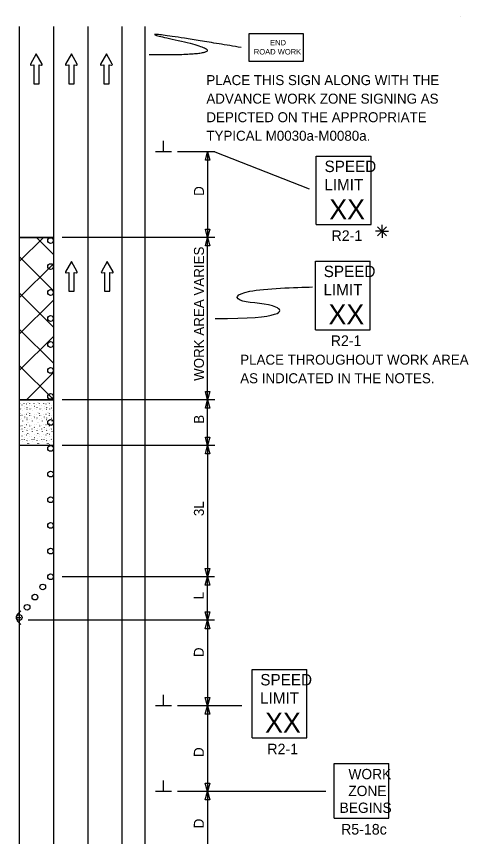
# Model space of a CAD drawing. Extents: x 16744 to 19504, y 5731 to 6974.
# Drawn here: x 17112 to 17429, y 6356 to 6931 of the extents above; entities that cross this region are included whole.
import ezdxf

# ---------------------------------------------------------------- set-up
doc = ezdxf.new("R2010")
doc.units = 0
for name, color, linetype in [('ALI_LEGAL_EX', 7, 'Continuous'), ('BORDER', 7, 'Continuous'), ('MT_SCRATCH_LEVEL_E', 7, 'Continuous'), ('PAVT_EDGE_EX', 7, 'Continuous'), ('TRAFFIC_SIGNS_PR', 7, 'Continuous'), ('TYPICAL_TEXT_DIMEN_PR', 7, 'Continuous')]:
    doc.layers.add(name, color=color, linetype=linetype)

msp = doc.modelspace()

# ---------------------------------------------------------------- linework, layer by layer
at = {"layer": 'ALI_LEGAL_EX'}
for p, q in [((17138.25, 6923.7), (17138.25, 6094.51)), ((17162.25, 6923.7), (17162.25, 6094.51))]:
    msp.add_line(p, q, dxfattribs=at)
for points in [[(17138.25, 6923.7), (17138.25, 6898.7)], [(17162.25, 6923.7), (17162.25, 6898.7)], [(17138.25, 6823.7), (17138.25, 6798.7)], [(17162.25, 6823.7), (17162.25, 6798.7)], [(17138.25, 6723.7), (17138.25, 6698.7)], [(17162.25, 6723.7), (17162.25, 6698.7)], [(17138.25, 6623.7), (17138.25, 6598.7)], [(17162.25, 6623.7), (17162.25, 6598.7)], [(17162.25, 6523.7), (17162.25, 6498.7)], [(17138.25, 6423.7), (17138.25, 6398.7)], [(17162.25, 6423.7), (17162.25, 6398.7)]]:
    msp.add_lwpolyline(points, dxfattribs=at)
at = {"layer": 'BORDER'}
msp.add_line((17423.55, 6930.8), (17423.55, 6930.8), dxfattribs=at)
at = {"layer": 'MT_SCRATCH_LEVEL_E'}
for p, q in [((17126.22, 6904.51), (17122.11, 6897.27)), ((17126.22, 6904.51), (17122.11, 6897.27)), ((17130.37, 6897.27), (17126.22, 6904.51)), ((17130.37, 6897.27), (17126.22, 6904.51)), ((17150.78, 6904.51), (17146.67, 6897.27)), ((17150.78, 6904.51), (17146.67, 6897.27)), ((17154.92, 6897.27), (17150.78, 6904.51)), ((17154.92, 6897.27), (17150.78, 6904.51)), ((17175.34, 6904.51), (17171.22, 6897.27)), ((17175.34, 6904.51), (17171.22, 6897.27)), ((17179.48, 6897.27), (17175.34, 6904.51)), ((17179.48, 6897.27), (17175.34, 6904.51)), ((17122.59, 6896.59), (17124.37, 6896.9)), ((17122.59, 6896.59), (17124.37, 6896.9)), ((17124.37, 6896.9), (17124.37, 6883.64)), ((17124.37, 6896.9), (17124.37, 6883.64)), ((17128.11, 6883.64), (17128.11, 6896.9)), ((17128.11, 6896.9), (17129.89, 6896.59)), ((17128.11, 6883.64), (17128.11, 6896.9)), ((17128.11, 6896.9), (17129.89, 6896.59)), ((17147.15, 6896.59), (17148.92, 6896.9)), ((17147.15, 6896.59), (17148.92, 6896.9)), ((17148.92, 6896.9), (17148.92, 6883.64)), ((17148.92, 6896.9), (17148.92, 6883.64)), ((17152.67, 6883.64), (17152.67, 6896.9)), ((17152.67, 6896.9), (17154.44, 6896.59)), ((17152.67, 6883.64), (17152.67, 6896.9)), ((17152.67, 6896.9), (17154.44, 6896.59)), ((17171.71, 6896.59), (17173.48, 6896.9)), ((17171.71, 6896.59), (17173.48, 6896.9)), ((17173.48, 6896.9), (17173.48, 6883.64)), ((17173.48, 6896.9), (17173.48, 6883.64)), ((17177.23, 6883.64), (17177.23, 6896.9)), ((17177.23, 6896.9), (17179, 6896.59)), ((17177.23, 6883.64), (17177.23, 6896.9)), ((17177.23, 6896.9), (17179, 6896.59)), ((17124.37, 6883.64), (17128.11, 6883.64)), ((17124.37, 6883.64), (17128.11, 6883.64)), ((17148.92, 6883.64), (17152.67, 6883.64)), ((17148.92, 6883.64), (17152.67, 6883.64)), ((17173.48, 6883.64), (17177.23, 6883.64)), ((17173.48, 6883.64), (17177.23, 6883.64)), ((17150.78, 6758.93), (17146.67, 6751.69)), ((17150.78, 6758.93), (17146.67, 6751.69)), ((17154.92, 6751.69), (17150.78, 6758.93)), ((17154.92, 6751.69), (17150.78, 6758.93)), ((17175.94, 6758.93), (17171.83, 6751.69)), ((17175.94, 6758.93), (17171.83, 6751.69)), ((17180.09, 6751.69), (17175.94, 6758.93)), ((17180.09, 6751.69), (17175.94, 6758.93)), ((17147.15, 6751.01), (17148.92, 6751.32)), ((17147.15, 6751.01), (17148.92, 6751.32)), ((17148.92, 6751.32), (17148.92, 6738.07)), ((17148.92, 6751.32), (17148.92, 6738.07)), ((17152.67, 6738.07), (17152.67, 6751.32)), ((17152.67, 6751.32), (17154.44, 6751.01)), ((17152.67, 6738.07), (17152.67, 6751.32)), ((17152.67, 6751.32), (17154.44, 6751.01)), ((17172.31, 6751.01), (17174.09, 6751.32)), ((17172.31, 6751.01), (17174.09, 6751.32)), ((17174.09, 6751.32), (17174.09, 6738.07)), ((17174.09, 6751.32), (17174.09, 6738.07)), ((17177.83, 6738.07), (17177.83, 6751.32)), ((17177.83, 6751.32), (17179.61, 6751.01)), ((17177.83, 6738.07), (17177.83, 6751.32)), ((17177.83, 6751.32), (17179.61, 6751.01)), ((17148.92, 6738.07), (17152.67, 6738.07)), ((17148.92, 6738.07), (17152.67, 6738.07)), ((17174.09, 6738.07), (17177.83, 6738.07)), ((17174.09, 6738.07), (17177.83, 6738.07))]:
    msp.add_line(p, q, dxfattribs=at)
for centre, start, end in [((17122.51, 6897.05), 150.42484, 279.96381), ((17122.51, 6897.05), 150.42484, 279.96381), ((17129.96, 6897.05), 260.03619, 29.77312), ((17129.96, 6897.05), 260.03619, 29.77312), ((17147.07, 6897.05), 150.42484, 279.96381), ((17147.07, 6897.05), 150.42484, 279.96381), ((17154.51, 6897.05), 260.03619, 29.77312), ((17154.51, 6897.05), 260.03619, 29.77312), ((17171.63, 6897.05), 150.42484, 279.96381), ((17171.63, 6897.05), 150.42484, 279.96381), ((17179.07, 6897.05), 260.03619, 29.77312), ((17179.07, 6897.05), 260.03619, 29.77312), ((17147.07, 6751.47), 150.42484, 279.96381), ((17147.07, 6751.47), 150.42484, 279.96381), ((17154.51, 6751.47), 260.03619, 29.77312), ((17154.51, 6751.47), 260.03619, 29.77312), ((17172.24, 6751.47), 150.42484, 279.96381), ((17172.24, 6751.47), 150.42484, 279.96381), ((17179.68, 6751.47), 260.03619, 29.77312), ((17179.68, 6751.47), 260.03619, 29.77312)]:
    msp.add_arc(centre, 0.463, start, end, dxfattribs=at)
at = {"layer": 'PAVT_EDGE_EX'}
for p, q in [((17114.25, 6923.7), (17114.25, 6094.51)), ((17186.25, 6923.7), (17186.25, 6094.51)), ((17202.25, 6923.7), (17202.25, 6094.51)), ((17114.25, 6775.79), (17138.25, 6775.79)), ((17114.25, 6758.89), (17131.15, 6775.79)), ((17138.34, 6775.79), (17114.34, 6775.79)), ((17138.25, 6763.97), (17126.44, 6775.79)), ((17138.25, 6738.52), (17114.25, 6762.52)), ((17114.25, 6733.43), (17138.25, 6757.43)), ((17138.25, 6713.06), (17114.25, 6737.06)), ((17114.25, 6707.98), (17138.25, 6731.98)), ((17138.25, 6687.61), (17114.25, 6711.61)), ((17114.25, 6682.52), (17138.25, 6706.52)), ((17138.25, 6662.15), (17114.25, 6686.15)), ((17119.25, 6662.06), (17138.34, 6681.15)), ((17138.25, 6662.06), (17114.25, 6662.06)), ((17138.34, 6662.06), (17114.34, 6662.06)), ((17114.34, 6662.06), (17138.34, 6662.06)), ((17114.65, 6658.24), (17114.6, 6658.16)), ((17114.73, 6659.51), (17114.68, 6659.62)), ((17116.18, 6658.38), (17116.13, 6658.3)), ((17116.75, 6661.7), (17116.7, 6661.82)), ((17117.8, 6659.21), (17117.74, 6659.33)), ((17119.25, 6659.06), (17119.19, 6658.98)), ((17120.12, 6660.44), (17120.06, 6660.36)), ((17120.85, 6660.47), (17120.8, 6660.39)), ((17121.54, 6658.24), (17121.48, 6658.16)), ((17121.62, 6659.51), (17121.56, 6659.62)), ((17123.07, 6658.38), (17123.01, 6658.3)), ((17123.64, 6661.7), (17123.58, 6661.82)), ((17124.68, 6659.21), (17124.63, 6659.33)), ((17126.13, 6659.06), (17126.08, 6658.98)), ((17127, 6660.44), (17126.95, 6660.36)), ((17127.74, 6660.47), (17127.69, 6660.39)), ((17128.42, 6658.24), (17128.37, 6658.16)), ((17128.5, 6659.51), (17128.45, 6659.62)), ((17129.95, 6658.38), (17129.9, 6658.3)), ((17130.52, 6661.7), (17130.47, 6661.82)), ((17131.57, 6659.21), (17131.52, 6659.33)), ((17133.02, 6659.06), (17132.97, 6658.98)), ((17133.89, 6660.44), (17133.84, 6660.36)), ((17134.63, 6660.47), (17134.58, 6660.39)), ((17135.31, 6658.24), (17135.26, 6658.16)), ((17135.39, 6659.51), (17135.34, 6659.62)), ((17136.84, 6658.38), (17136.79, 6658.3)), ((17137.41, 6661.7), (17137.36, 6661.82)), ((17138.34, 6662.06), (17138.34, 6662.06)), ((17114.85, 6655.6), (17114.83, 6655.48)), ((17116.13, 6656.17), (17116.08, 6656.09)), ((17116.75, 6654.42), (17116.7, 6654.54)), ((17117.93, 6655.92), (17117.88, 6656.04)), ((17117.97, 6657.32), (17117.92, 6657.24)), ((17119.71, 6655.25), (17119.65, 6655.18)), ((17119.89, 6656.45), (17119.84, 6656.57)), ((17120.12, 6653.15), (17120.06, 6653.07)), ((17120.85, 6653.18), (17120.8, 6653.11)), ((17121.74, 6655.6), (17121.72, 6655.48)), ((17123.02, 6656.17), (17122.97, 6656.09)), ((17123.64, 6654.42), (17123.58, 6654.54)), ((17124.81, 6655.92), (17124.76, 6656.04)), ((17124.86, 6657.32), (17124.81, 6657.24)), ((17126.59, 6655.25), (17126.54, 6655.18)), ((17126.78, 6656.45), (17126.73, 6656.57)), ((17127, 6653.15), (17126.95, 6653.07)), ((17127.74, 6653.18), (17127.69, 6653.11)), ((17128.62, 6655.6), (17128.61, 6655.48)), ((17129.9, 6656.17), (17129.85, 6656.09)), ((17130.52, 6654.42), (17130.47, 6654.54)), ((17131.7, 6655.92), (17131.65, 6656.04)), ((17131.74, 6657.32), (17131.69, 6657.24)), ((17133.48, 6655.25), (17133.43, 6655.18)), ((17133.67, 6656.45), (17133.62, 6656.57)), ((17133.89, 6653.15), (17133.84, 6653.07)), ((17134.63, 6653.18), (17134.58, 6653.11)), ((17135.51, 6655.6), (17135.5, 6655.48)), ((17136.79, 6656.17), (17136.74, 6656.09)), ((17137.41, 6654.42), (17137.36, 6654.54)), ((17114.65, 6650.96), (17114.6, 6650.88)), ((17114.73, 6652.22), (17114.68, 6652.34)), ((17114.85, 6648.31), (17114.83, 6648.19)), ((17116.13, 6648.89), (17116.08, 6648.81)), ((17116.18, 6651.1), (17116.13, 6651.02)), ((17116.75, 6647.13), (17116.7, 6647.25)), ((17117.8, 6651.93), (17117.74, 6652.04)), ((17117.93, 6648.64), (17117.88, 6648.75)), ((17117.97, 6650.04), (17117.92, 6649.96)), ((17119.25, 6651.77), (17119.19, 6651.7)), ((17119.71, 6647.97), (17119.65, 6647.89)), ((17119.89, 6649.17), (17119.84, 6649.28)), ((17121.54, 6650.96), (17121.48, 6650.88)), ((17121.62, 6652.22), (17121.56, 6652.34)), ((17121.74, 6648.31), (17121.72, 6648.19)), ((17123.02, 6648.89), (17122.97, 6648.81)), ((17123.07, 6651.1), (17123.01, 6651.02)), ((17123.64, 6647.13), (17123.58, 6647.25)), ((17124.68, 6651.93), (17124.63, 6652.04)), ((17124.81, 6648.64), (17124.76, 6648.75)), ((17124.86, 6650.04), (17124.81, 6649.96)), ((17126.13, 6651.77), (17126.08, 6651.7)), ((17126.59, 6647.97), (17126.54, 6647.89)), ((17126.78, 6649.17), (17126.73, 6649.28)), ((17128.42, 6650.96), (17128.37, 6650.88)), ((17128.5, 6652.22), (17128.45, 6652.34)), ((17128.62, 6648.31), (17128.61, 6648.19)), ((17129.9, 6648.89), (17129.85, 6648.81)), ((17129.95, 6651.1), (17129.9, 6651.02)), ((17130.52, 6647.13), (17130.47, 6647.25)), ((17131.57, 6651.93), (17131.52, 6652.04)), ((17131.7, 6648.64), (17131.65, 6648.75)), ((17131.74, 6650.04), (17131.69, 6649.96)), ((17133.02, 6651.77), (17132.97, 6651.7)), ((17133.48, 6647.97), (17133.43, 6647.89)), ((17133.67, 6649.17), (17133.62, 6649.28)), ((17135.31, 6650.96), (17135.26, 6650.88)), ((17135.39, 6652.22), (17135.34, 6652.34)), ((17135.51, 6648.31), (17135.5, 6648.19)), ((17136.79, 6648.89), (17136.74, 6648.81)), ((17136.84, 6651.1), (17136.79, 6651.02)), ((17137.41, 6647.13), (17137.36, 6647.25)), ((17114.65, 6643.67), (17114.6, 6643.59)), ((17114.73, 6644.94), (17114.68, 6645.05)), ((17114.85, 6641.03), (17114.83, 6640.91)), ((17116.13, 6641.6), (17116.08, 6641.52)), ((17116.18, 6643.81), (17116.13, 6643.73)), ((17117.8, 6644.64), (17117.74, 6644.76)), ((17117.93, 6641.35), (17117.88, 6641.47)), ((17117.97, 6642.75), (17117.92, 6642.67)), ((17119.25, 6644.49), (17119.19, 6644.41)), ((17119.89, 6641.88), (17119.84, 6642)), ((17120.12, 6645.87), (17120.06, 6645.79)), ((17120.85, 6645.9), (17120.8, 6645.82)), ((17121.54, 6643.67), (17121.48, 6643.59)), ((17121.62, 6644.94), (17121.56, 6645.05)), ((17121.74, 6641.03), (17121.72, 6640.91)), ((17123.02, 6641.6), (17122.97, 6641.52)), ((17123.07, 6643.81), (17123.01, 6643.73)), ((17124.68, 6644.64), (17124.63, 6644.76)), ((17124.81, 6641.35), (17124.76, 6641.47)), ((17124.86, 6642.75), (17124.81, 6642.67)), ((17126.13, 6644.49), (17126.08, 6644.41)), ((17126.78, 6641.88), (17126.73, 6642)), ((17127, 6645.87), (17126.95, 6645.79)), ((17127.74, 6645.9), (17127.69, 6645.82)), ((17128.42, 6643.67), (17128.37, 6643.59)), ((17128.5, 6644.94), (17128.45, 6645.05)), ((17128.62, 6641.03), (17128.61, 6640.91)), ((17129.9, 6641.6), (17129.85, 6641.52)), ((17129.95, 6643.81), (17129.9, 6643.73)), ((17131.57, 6644.64), (17131.52, 6644.76)), ((17131.7, 6641.35), (17131.65, 6641.47)), ((17131.74, 6642.75), (17131.69, 6642.67)), ((17133.02, 6644.49), (17132.97, 6644.41)), ((17133.67, 6641.88), (17133.62, 6642)), ((17133.89, 6645.87), (17133.84, 6645.79)), ((17134.63, 6645.9), (17134.58, 6645.82)), ((17135.31, 6643.67), (17135.26, 6643.59)), ((17135.39, 6644.94), (17135.34, 6645.05)), ((17135.51, 6641.03), (17135.5, 6640.91)), ((17136.79, 6641.6), (17136.74, 6641.52)), ((17136.84, 6643.81), (17136.79, 6643.73)), ((17114.65, 6636.39), (17114.6, 6636.31)), ((17114.73, 6637.65), (17114.68, 6637.77)), ((17116.18, 6636.53), (17116.13, 6636.45)), ((17116.75, 6639.85), (17116.7, 6639.97)), ((17117.8, 6637.36), (17117.74, 6637.47)), ((17117.97, 6635.47), (17117.92, 6635.39)), ((17119.25, 6637.2), (17119.19, 6637.13)), ((17119.71, 6640.68), (17119.65, 6640.61)), ((17120.12, 6638.58), (17120.06, 6638.51)), ((17120.85, 6638.61), (17120.8, 6638.53)), ((17121.54, 6636.39), (17121.48, 6636.31)), ((17121.62, 6637.65), (17121.56, 6637.77)), ((17123.07, 6636.53), (17123.01, 6636.45)), ((17123.64, 6639.85), (17123.58, 6639.97)), ((17124.68, 6637.36), (17124.63, 6637.47)), ((17124.86, 6635.47), (17124.81, 6635.39)), ((17126.13, 6637.2), (17126.08, 6637.13)), ((17126.59, 6640.68), (17126.54, 6640.61)), ((17127, 6638.58), (17126.95, 6638.51)), ((17127.74, 6638.61), (17127.69, 6638.53)), ((17128.42, 6636.39), (17128.37, 6636.31)), ((17128.5, 6637.65), (17128.45, 6637.77)), ((17129.95, 6636.53), (17129.9, 6636.45)), ((17130.52, 6639.85), (17130.47, 6639.97)), ((17131.57, 6637.36), (17131.52, 6637.47)), ((17131.74, 6635.47), (17131.69, 6635.39)), ((17133.02, 6637.2), (17132.97, 6637.13)), ((17133.48, 6640.68), (17133.43, 6640.61)), ((17133.89, 6638.58), (17133.84, 6638.51)), ((17134.63, 6638.61), (17134.58, 6638.53)), ((17135.31, 6636.39), (17135.26, 6636.31)), ((17135.39, 6637.65), (17135.34, 6637.77)), ((17136.84, 6636.53), (17136.79, 6636.45)), ((17137.41, 6639.85), (17137.36, 6639.97)), ((17138.25, 6630), (17114.25, 6630)), ((17138.34, 6630), (17114.34, 6630)), ((17114.73, 6630.37), (17114.68, 6630.48)), ((17114.85, 6633.74), (17114.83, 6633.62)), ((17116.13, 6634.32), (17116.08, 6634.24)), ((17116.75, 6632.56), (17116.7, 6632.68)), ((17117.8, 6630.07), (17117.74, 6630.19)), ((17117.93, 6634.07), (17117.88, 6634.18)), ((17119.71, 6633.4), (17119.65, 6633.32)), ((17119.89, 6634.6), (17119.84, 6634.71)), ((17120.12, 6631.3), (17120.06, 6631.22)), ((17120.85, 6631.33), (17120.8, 6631.25)), ((17121.62, 6630.37), (17121.56, 6630.48)), ((17121.74, 6633.74), (17121.72, 6633.62)), ((17123.02, 6634.32), (17122.97, 6634.24)), ((17123.64, 6632.56), (17123.58, 6632.68)), ((17124.68, 6630.07), (17124.63, 6630.19)), ((17124.81, 6634.07), (17124.76, 6634.18)), ((17126.59, 6633.4), (17126.54, 6633.32)), ((17126.78, 6634.6), (17126.73, 6634.71)), ((17127, 6631.3), (17126.95, 6631.22)), ((17127.74, 6631.33), (17127.69, 6631.25)), ((17128.5, 6630.37), (17128.45, 6630.48)), ((17128.62, 6633.74), (17128.61, 6633.62)), ((17129.9, 6634.32), (17129.85, 6634.24)), ((17130.52, 6632.56), (17130.47, 6632.68)), ((17131.57, 6630.07), (17131.52, 6630.19)), ((17131.7, 6634.07), (17131.65, 6634.18)), ((17133.48, 6633.4), (17133.43, 6633.32)), ((17133.67, 6634.6), (17133.62, 6634.71)), ((17133.89, 6631.3), (17133.84, 6631.22)), ((17134.63, 6631.33), (17134.58, 6631.25)), ((17135.39, 6630.37), (17135.34, 6630.48)), ((17135.51, 6633.74), (17135.5, 6633.62)), ((17136.79, 6634.32), (17136.74, 6634.24)), ((17137.41, 6632.56), (17137.36, 6632.68))]:
    msp.add_line(p, q, dxfattribs=at)
at = {"layer": 'TRAFFIC_SIGNS_PR'}
for p, q in [((17322.58, 6832.81), (17360.98, 6832.81)), ((17322.58, 6784.81), (17322.58, 6832.81)), ((17360.98, 6784.81), (17360.98, 6832.81)), ((17322.58, 6784.81), (17360.98, 6784.81)), ((17322.02, 6759.19), (17360.42, 6759.19)), ((17322.02, 6711.19), (17322.02, 6759.19)), ((17360.42, 6711.19), (17360.42, 6759.19)), ((17322.02, 6711.19), (17360.42, 6711.19)), ((17115.4, 6514.19), (17112.58, 6511.37)), ((17112.58, 6509.34), (17115.4, 6509.34)), ((17115.4, 6504.49), (17112.58, 6507.31)), ((17277.56, 6472.95), (17315.96, 6472.95)), ((17277.56, 6424.95), (17277.56, 6472.95)), ((17315.96, 6424.95), (17315.96, 6472.95)), ((17277.56, 6424.95), (17315.96, 6424.95)), ((17335.13, 6368.69), (17335.13, 6407.09)), ((17335.13, 6407.09), (17373.53, 6407.09)), ((17373.53, 6368.69), (17373.53, 6407.09)), ((17335.13, 6368.69), (17373.53, 6368.69))]:
    msp.add_line(p, q, dxfattribs=at)
msp.add_lwpolyline([(17275.16, 6899.37), (17313.56, 6899.37), (17313.56, 6918.57), (17275.16, 6918.57)], close=True, dxfattribs=at)
for centre in [(17136.24, 6773.67), (17136.24, 6755.45), (17136.24, 6737.24), (17136.24, 6719.02), (17136.24, 6700.81), (17136.24, 6682.59), (17136.24, 6664.38), (17136.24, 6646.17), (17136.24, 6627.95), (17136.24, 6609.95), (17136.24, 6591.95), (17136.24, 6573.95), (17136.24, 6555.95), (17136.24, 6537.95), (17136.24, 6537.95), (17136.24, 6537.95), (17136.24, 6537.95), (17130.74, 6530.82), (17125.24, 6523.69), (17119.75, 6516.56), (17114.25, 6509.44)]:
    msp.add_circle(centre, 2, dxfattribs=at)
at = {"layer": 'TYPICAL_TEXT_DIMEN_PR'}
for p, q in [((17215.46, 6835.79), (17215.46, 6843.57)), ((17221.09, 6835.79), (17209.84, 6835.79)), ((17251.34, 6835.79), (17225.34, 6835.79)), ((17244.77, 6829.93), (17246.34, 6835.79)), ((17246.34, 6835.79), (17246.34, 6775.79)), ((17246.34, 6835.79), (17247.91, 6829.93)), ((17251.34, 6835.79), (17317.69, 6809.94)), ((17246.34, 6829.93), (17244.77, 6829.93)), ((17247.91, 6829.93), (17246.34, 6829.93)), ((17246.34, 6790.66), (17246.34, 6786.89)), ((17246.34, 6775.79), (17244.77, 6781.65)), ((17244.77, 6781.65), (17246.34, 6781.65)), ((17246.34, 6781.65), (17247.91, 6781.65)), ((17247.91, 6781.65), (17246.34, 6775.79)), ((17368.73, 6780.15), (17364.19, 6780.15)), ((17365.54, 6783.34), (17371.91, 6776.96)), ((17371.91, 6783.34), (17365.54, 6776.96)), ((17368.73, 6780.15), (17368.73, 6784.6)), ((17368.73, 6780.15), (17371.91, 6780.15)), ((17368.73, 6780.15), (17373.2, 6780.15)), ((17368.73, 6780.15), (17368.73, 6775.65)), ((17251.34, 6775.79), (17144.33, 6775.79)), ((17244.77, 6769.93), (17246.34, 6775.79)), ((17246.34, 6662.06), (17246.34, 6775.79)), ((17246.34, 6775.79), (17247.91, 6769.93)), ((17246.34, 6769.93), (17244.77, 6769.93)), ((17247.91, 6769.93), (17246.34, 6769.93)), ((17246.34, 6662.06), (17244.77, 6667.92)), ((17244.77, 6667.92), (17246.34, 6667.92)), ((17246.34, 6667.92), (17247.91, 6667.92)), ((17247.91, 6667.92), (17246.34, 6662.06)), ((17251.34, 6662.06), (17144.33, 6662.06)), ((17244.77, 6656.2), (17246.34, 6662.06)), ((17246.34, 6630), (17246.34, 6662.06)), ((17246.34, 6662.06), (17247.91, 6656.2)), ((17246.34, 6656.2), (17244.77, 6656.2)), ((17247.91, 6656.2), (17246.34, 6656.2)), ((17246.34, 6630), (17244.77, 6635.86)), ((17244.77, 6635.86), (17246.34, 6635.86)), ((17246.34, 6635.86), (17247.91, 6635.86)), ((17247.91, 6635.86), (17246.34, 6630)), ((17251.34, 6630), (17144.33, 6630)), ((17244.77, 6624.14), (17246.34, 6630)), ((17246.34, 6630), (17246.25, 6537.95)), ((17246.34, 6630), (17247.91, 6624.14)), ((17246.34, 6624.14), (17244.77, 6624.14)), ((17247.91, 6624.14), (17246.34, 6624.14)), ((17246.25, 6537.95), (17244.68, 6543.81)), ((17244.68, 6543.81), (17246.25, 6543.81)), ((17246.25, 6543.81), (17247.82, 6543.81)), ((17247.82, 6543.81), (17246.25, 6537.95)), ((17251.25, 6537.95), (17144.33, 6537.95)), ((17244.68, 6532.09), (17246.25, 6537.95)), ((17246.25, 6507.44), (17246.25, 6537.95)), ((17246.25, 6537.95), (17247.82, 6532.09)), ((17246.25, 6532.09), (17244.68, 6532.09)), ((17247.82, 6532.09), (17246.25, 6532.09)), ((17246.25, 6507.44), (17244.68, 6513.3)), ((17244.68, 6513.3), (17246.25, 6513.3)), ((17246.25, 6513.3), (17247.82, 6513.3)), ((17247.82, 6513.3), (17246.25, 6507.44)), ((17251.25, 6507.44), (17120.51, 6507.44)), ((17251.25, 6507.44), (17205.55, 6507.44)), ((17244.68, 6501.57), (17246.25, 6507.44)), ((17246.25, 6507.44), (17246.25, 6437.44)), ((17246.25, 6507.44), (17247.82, 6501.57)), ((17246.25, 6501.57), (17244.68, 6501.57)), ((17247.82, 6501.57), (17246.25, 6501.57)), ((17246.25, 6472.31), (17246.25, 6468.54)), ((17215.38, 6447.44), (17215.38, 6455.22)), ((17246.25, 6447.44), (17244.68, 6453.3)), ((17244.68, 6453.3), (17246.25, 6453.3)), ((17246.25, 6453.3), (17247.82, 6453.3)), ((17247.82, 6453.3), (17246.25, 6447.44)), ((17221, 6447.44), (17209.75, 6447.44)), ((17270.33, 6447.44), (17225.25, 6447.44)), ((17244.68, 6441.57), (17246.25, 6447.44)), ((17246.25, 6447.44), (17246.25, 6377.44)), ((17246.25, 6447.44), (17247.82, 6441.57)), ((17246.25, 6441.57), (17244.68, 6441.57)), ((17247.82, 6441.57), (17246.25, 6441.57)), ((17215.38, 6387.44), (17215.38, 6395.22)), ((17246.25, 6387.44), (17244.68, 6393.3)), ((17244.68, 6393.3), (17246.25, 6393.3)), ((17246.25, 6393.3), (17247.82, 6393.3)), ((17247.82, 6393.3), (17246.25, 6387.44)), ((17221, 6387.44), (17209.75, 6387.44)), ((17329.35, 6387.44), (17225.25, 6387.44)), ((17244.68, 6381.57), (17246.25, 6387.44)), ((17246.25, 6387.44), (17247.82, 6381.57)), ((17246.25, 6387.44), (17246.25, 6327.44)), ((17246.25, 6381.57), (17244.68, 6381.57)), ((17247.82, 6381.57), (17246.25, 6381.57))]:
    msp.add_line(p, q, dxfattribs=at)
for points, degree in [([(17269.81, 6908.97), (17176.92, 6924.6), (17274.83, 6903.09), (17205.42, 6903.8)], 2), ([(17251.66, 6718.92), (17300.13, 6718.92), (17300.13, 6729.68), (17265.21, 6729.68), (17265.21, 6739.34), (17308.07, 6740.86), (17319.98, 6741.12)], 3), ([(17342.39, 6731.6), (17342.4, 6731.6), (17342.41, 6731.6), (17342.41, 6731.6)], 2)]:
    msp.add_open_spline(points, degree=degree, dxfattribs=at)

# ---------------------------------------------------------------- texts
at = {"layer": 'TRAFFIC_SIGNS_PR'}
for s, height, p in [('END', 3.831, (17290.16, 6910.5)), ('ROAD WORK', 3.831, (17278.77, 6904.11)), ('PLACE THIS SIGN ALONG WITH THE', 7, (17245.49, 6882.63)), ('ADVANCE WORK ZONE SIGNING AS', 7, (17245.49, 6869.63)), ('DEPICTED ON THE APPROPRIATE', 7, (17245.49, 6856.63)), ('TYPICAL M0030a-M0080a.', 7, (17245.49, 6843.63)), ('SPEED', 8, (17328.34, 6821.68)), ('LIMIT', 8, (17328.18, 6808.88)), ('XX', 14.031, (17331.69, 6788.57)), ('R2-1', 7.44, (17333.25, 6773.37)), ('SPEED', 8, (17327.79, 6748.06)), ('LIMIT', 8, (17327.63, 6735.26)), ('XX', 14.031, (17331.14, 6714.95)), ('R2-1', 7.44, (17332.7, 6699.75)), ('PLACE THROUGHOUT WORK AREA', 7, (17269.22, 6686.65)), ('AS INDICATED IN THE NOTES.', 7, (17269.22, 6673.65)), ('SPEED', 8, (17283.32, 6461.81)), ('LIMIT', 8, (17283.16, 6449.01)), ('XX', 14.031, (17286.67, 6428.71)), ('R2-1', 7.44, (17288.23, 6413.51)), ('WORK', 7.217, (17345.13, 6396.05)), ('ZONE', 7.217, (17345.01, 6384.24)), ('BEGINS', 7.217, (17338.94, 6372.44)), ('R5-18c', 7.44, (17339.94, 6357.25))]:
    msp.add_text(s, height=height, dxfattribs=at).set_placement(p)
at = {"layer": 'TYPICAL_TEXT_DIMEN_PR'}
for s, p in [('D', (17243.78, 6805.01)), ('WORK AREA VARIES', (17243.78, 6675.28)), ('B', (17243.78, 6645.27)), ('3L', (17243.74, 6580.48)), ('L', (17243.69, 6522.05)), ('D', (17243.69, 6481.66)), ('D', (17243.69, 6411.66)), ('D', (17243.69, 6361.66))]:
    msp.add_text(s, height=7, rotation=90, dxfattribs=at).set_placement(p)

doc.saveas('drawing.dxf')
